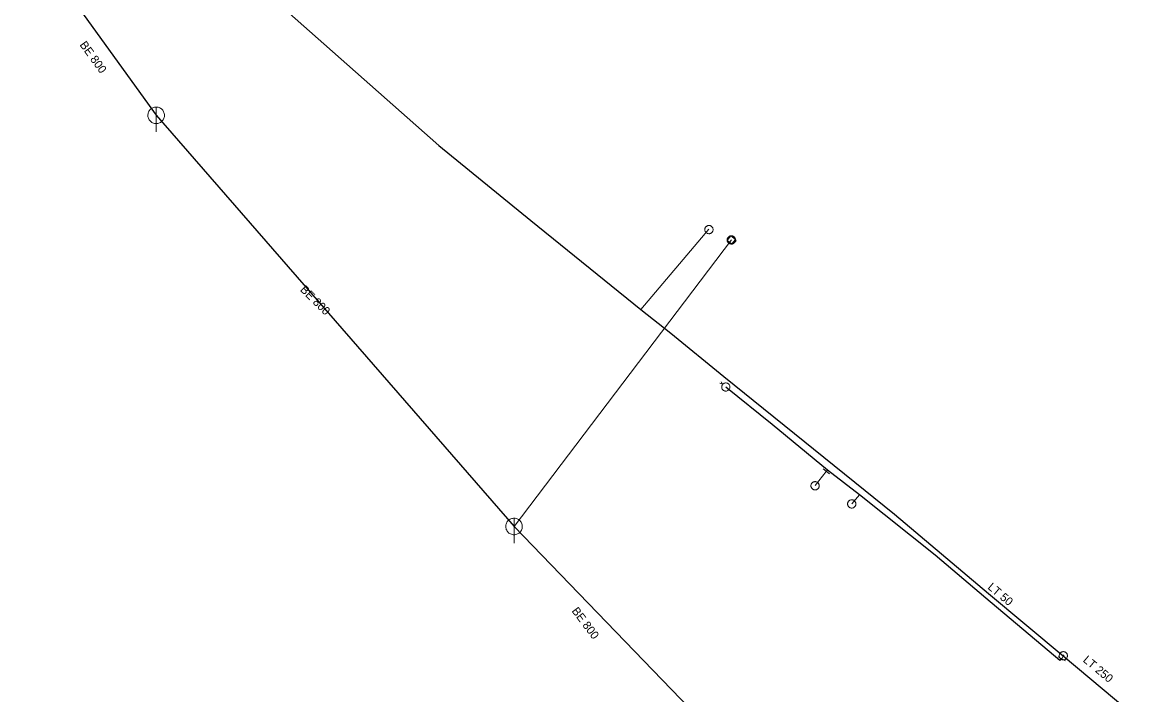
# Model space of a CAD drawing. Extents: x -807203 to -805207, y -993656 to -992505.
# Drawn here: x -805956 to -805822.4, y -993433.3 to -993352 of the extents above; entities that cross this region are included whole.
import ezdxf

# ---------------------------------------------------------------- set-up
doc = ezdxf.new("R2010")
doc.units = 0
doc.header["$LTSCALE"] = 0.4
doc.header["$PDMODE"] = 32
doc.header["$PDSIZE"] = 0.2
for name, color, linetype, lineweight in [('1', 7, 'Continuous', 13), ('11', 7, 'Continuous', 13), ('13', 7, 'Continuous', 13), ('14', 7, 'Continuous', 25), ('17', 7, 'Continuous', 25), ('22', 7, 'Continuous', 13), ('23', 7, 'Continuous', 13), ('34', 7, 'Continuous', 13), ('47', 7, 'Continuous', 13)]:
    doc.layers.add(name, color=color, linetype=linetype, lineweight=lineweight)

msp = doc.modelspace()

# ---------------------------------------------------------------- linework, layer by layer
at = {"layer": '11'}
msp.add_line((-805870.333, -993378.295), (-805896.59, -993412.94), dxfattribs=at)
at = {"layer": '13'}
for p, q in [((-805881.298, -993386.71), (-805873.059, -993377.03)), ((-805858.888, -993406.276), (-805860.249, -993407.99)), ((-805854.899, -993409.109), (-805855.822, -993410.186))]:
    msp.add_line(p, q, dxfattribs=at)
at = {"layer": '14'}
for p, q in [((-805951.2, -993347.419), (-805939.8, -993363.25)), ((-805939.8, -993363.25), (-805896.59, -993412.94)), ((-805896.59, -993412.94), (-805874.241, -993436.109))]:
    msp.add_line(p, q, dxfattribs=at)
at = {"layer": '14', "lineweight": 13}
for p, q in [((-805858.888, -993406.276), (-805858.765, -993406.12)), ((-805830.275, -993428.564), (-805830.473, -993428.943))]:
    msp.add_line(p, q, dxfattribs=at)
at = {"layer": '17'}
msp.add_line((-805830.275, -993428.564), (-805822.361, -993435.213), dxfattribs=at)
for points in [[(-805980.27, -993297.811), (-805964.539, -993313.096), (-805944.059, -993332.754), (-805925.796, -993349.072), (-805905.688, -993366.883), (-805894.556, -993375.978), (-805881.298, -993386.71), (-805877.651, -993389.561), (-805871.269, -993394.798), (-805850.666, -993411.467), (-805839.3, -993421.037), (-805830.275, -993428.564)], [(-805830.473, -993428.943), (-805830.693, -993429.142), (-805839.629, -993421.616), (-805845.743, -993416.397), (-805854.899, -993409.109), (-805858.765, -993406.12), (-805865.421, -993400.636), (-805871.024, -993396.088)]]:
    msp.add_lwpolyline(points, dxfattribs=at)
at = {"layer": '22'}
for p, q in [((-805939.8, -993365.25), (-805939.799, -993362.25)), ((-805896.59, -993414.94), (-805896.589, -993411.94))]:
    msp.add_line(p, q, dxfattribs=at)
for points in [[(-805938.8, -993363.25), (-805938.805, -993363.141), (-805938.823, -993363.033), (-805938.853, -993362.927), (-805938.893, -993362.826), (-805938.945, -993362.729), (-805939.007, -993362.639), (-805939.079, -993362.556), (-805939.159, -993362.482), (-805939.247, -993362.416), (-805939.341, -993362.361), (-805939.441, -993362.316), (-805939.546, -993362.283), (-805939.653, -993362.261), (-805939.762, -993362.251), (-805939.872, -993362.253), (-805939.98, -993362.267), (-805940.087, -993362.292), (-805940.19, -993362.329), (-805940.288, -993362.378), (-805940.38, -993362.436), (-805940.466, -993362.505), (-805940.543, -993362.582), (-805940.612, -993362.668), (-805940.671, -993362.76), (-805940.719, -993362.858), (-805940.756, -993362.961), (-805940.782, -993363.068), (-805940.796, -993363.176), (-805940.799, -993363.286), (-805940.789, -993363.395), (-805940.768, -993363.502), (-805940.734, -993363.606), (-805940.69, -993363.706), (-805940.635, -993363.801), (-805940.569, -993363.889), (-805940.495, -993363.969), (-805940.412, -993364.041), (-805940.322, -993364.103), (-805940.226, -993364.155), (-805940.124, -993364.196), (-805940.019, -993364.226), (-805939.911, -993364.244), (-805939.801, -993364.25), (-805939.692, -993364.244), (-805939.584, -993364.226), (-805939.479, -993364.197), (-805939.377, -993364.156), (-805939.28, -993364.104), (-805939.19, -993364.042), (-805939.107, -993363.971), (-805939.032, -993363.891), (-805938.967, -993363.803), (-805938.911, -993363.709), (-805938.867, -993363.609), (-805938.833, -993363.505), (-805938.811, -993363.397), (-805938.801, -993363.288)], [(-805870.047, -993377.922), (-805870.089, -993377.891), (-805870.137, -993377.866), (-805870.184, -993377.845), (-805870.234, -993377.829), (-805870.285, -993377.819), (-805870.339, -993377.814), (-805870.39, -993377.815), (-805870.442, -993377.822), (-805870.493, -993377.831), (-805870.543, -993377.848), (-805870.591, -993377.87), (-805870.634, -993377.897), (-805870.677, -993377.927), (-805870.717, -993377.964), (-805870.749, -993378.003), (-805870.78, -993378.045), (-805870.806, -993378.092), (-805870.827, -993378.14), (-805870.843, -993378.189), (-805870.852, -993378.24), (-805870.857, -993378.293), (-805870.857, -993378.345), (-805870.851, -993378.397), (-805870.841, -993378.448), (-805870.824, -993378.497), (-805870.801, -993378.546), (-805870.775, -993378.59), (-805870.745, -993378.632), (-805870.707, -993378.67), (-805870.669, -993378.704), (-805870.626, -993378.734), (-805870.58, -993378.761), (-805870.533, -993378.783), (-805870.483, -993378.797), (-805870.432, -993378.807), (-805870.379, -993378.813), (-805870.327, -993378.812), (-805870.275, -993378.806), (-805870.224, -993378.795), (-805870.174, -993378.779), (-805870.126, -993378.756), (-805870.082, -993378.73), (-805870.039, -993378.699), (-805870.001, -993378.663), (-805869.967, -993378.625), (-805869.937, -993378.582), (-805869.911, -993378.535), (-805869.889, -993378.488), (-805869.875, -993378.438), (-805869.864, -993378.386), (-805869.859, -993378.334), (-805869.859, -993378.283), (-805869.866, -993378.231), (-805869.876, -993378.179), (-805869.893, -993378.129), (-805869.915, -993378.081), (-805869.941, -993378.037), (-805869.972, -993377.995), (-805870.009, -993377.955)], [(-805870.85, -993378.37), (-805870.41, -993377.815), (-805869.867, -993378.246), (-805870.308, -993378.801)], [(-805895.59, -993412.94), (-805895.595, -993412.831), (-805895.613, -993412.723), (-805895.643, -993412.617), (-805895.683, -993412.516), (-805895.735, -993412.419), (-805895.797, -993412.329), (-805895.869, -993412.246), (-805895.949, -993412.172), (-805896.037, -993412.106), (-805896.131, -993412.051), (-805896.231, -993412.006), (-805896.336, -993411.973), (-805896.443, -993411.951), (-805896.552, -993411.941), (-805896.662, -993411.943), (-805896.77, -993411.957), (-805896.877, -993411.982), (-805896.98, -993412.019), (-805897.078, -993412.068), (-805897.17, -993412.126), (-805897.256, -993412.195), (-805897.333, -993412.272), (-805897.402, -993412.358), (-805897.461, -993412.45), (-805897.509, -993412.548), (-805897.546, -993412.651), (-805897.572, -993412.758), (-805897.586, -993412.866), (-805897.589, -993412.976), (-805897.579, -993413.085), (-805897.558, -993413.192), (-805897.524, -993413.296), (-805897.48, -993413.396), (-805897.425, -993413.491), (-805897.359, -993413.579), (-805897.285, -993413.659), (-805897.202, -993413.731), (-805897.112, -993413.793), (-805897.016, -993413.845), (-805896.914, -993413.886), (-805896.809, -993413.916), (-805896.701, -993413.934), (-805896.591, -993413.94), (-805896.482, -993413.934), (-805896.374, -993413.916), (-805896.269, -993413.887), (-805896.167, -993413.846), (-805896.07, -993413.794), (-805895.98, -993413.732), (-805895.897, -993413.661), (-805895.822, -993413.581), (-805895.757, -993413.493), (-805895.701, -993413.399), (-805895.657, -993413.299), (-805895.623, -993413.195), (-805895.601, -993413.087), (-805895.591, -993412.978)]]:
    msp.add_lwpolyline(points, close=True, dxfattribs=at)
msp.add_point((-805869.868, -993378.416), dxfattribs=at)
at = {"layer": '23'}
for points in [[(-805872.736, -993376.678), (-805872.778, -993376.646), (-805872.824, -993376.619), (-805872.871, -993376.598), (-805872.92, -993376.581), (-805872.971, -993376.57), (-805873.024, -993376.564), (-805873.076, -993376.563), (-805873.127, -993376.568), (-805873.179, -993376.578), (-805873.229, -993376.593), (-805873.277, -993376.613), (-805873.324, -993376.64), (-805873.366, -993376.669), (-805873.404, -993376.704), (-805873.44, -993376.741), (-805873.472, -993376.785), (-805873.499, -993376.828), (-805873.521, -993376.878), (-805873.538, -993376.925), (-805873.55, -993376.976), (-805873.555, -993377.03), (-805873.555, -993377.082), (-805873.551, -993377.135), (-805873.541, -993377.186), (-805873.525, -993377.235), (-805873.504, -993377.283), (-805873.479, -993377.328), (-805873.448, -993377.371), (-805873.413, -993377.41), (-805873.376, -993377.446), (-805873.334, -993377.478), (-805873.289, -993377.505), (-805873.241, -993377.527), (-805873.192, -993377.544), (-805873.142, -993377.554), (-805873.089, -993377.56), (-805873.037, -993377.562), (-805872.984, -993377.557), (-805872.933, -993377.546)], [(-805873.521, -993376.878), (-805873.538, -993376.925), (-805873.55, -993376.976), (-805873.555, -993377.03), (-805873.555, -993377.082), (-805873.551, -993377.135), (-805873.541, -993377.186), (-805873.525, -993377.235), (-805873.504, -993377.283), (-805873.479, -993377.328), (-805873.448, -993377.371), (-805873.413, -993377.41), (-805873.376, -993377.446), (-805873.334, -993377.478), (-805873.289, -993377.505), (-805873.241, -993377.527), (-805873.192, -993377.544), (-805873.142, -993377.554), (-805873.089, -993377.56), (-805873.037, -993377.562), (-805872.984, -993377.557), (-805872.933, -993377.546), (-805872.884, -993377.532), (-805872.835, -993377.51), (-805872.789, -993377.486), (-805872.747, -993377.454), (-805872.708, -993377.42), (-805872.672, -993377.382), (-805872.642, -993377.34), (-805872.614, -993377.295), (-805872.592, -993377.247), (-805872.576, -993377.197), (-805872.564, -993377.146), (-805872.557, -993377.095), (-805872.558, -993377.042), (-805872.561, -993376.991), (-805872.572, -993376.94), (-805872.587, -993376.888), (-805872.608, -993376.84), (-805872.634, -993376.795)], [(-805872.933, -993377.546), (-805872.884, -993377.532), (-805872.835, -993377.51), (-805872.789, -993377.486), (-805872.747, -993377.454), (-805872.708, -993377.42), (-805872.672, -993377.382), (-805872.642, -993377.34), (-805872.614, -993377.295), (-805872.592, -993377.247), (-805872.576, -993377.197), (-805872.564, -993377.146), (-805872.557, -993377.095), (-805872.558, -993377.042), (-805872.561, -993376.991), (-805872.572, -993376.94), (-805872.587, -993376.888), (-805872.608, -993376.84), (-805872.634, -993376.795), (-805872.665, -993376.753), (-805872.698, -993376.714), (-805872.736, -993376.678), (-805872.778, -993376.646), (-805872.824, -993376.619), (-805872.871, -993376.598), (-805872.92, -993376.581), (-805872.971, -993376.57), (-805873.024, -993376.564), (-805873.076, -993376.563), (-805873.127, -993376.568), (-805873.179, -993376.578), (-805873.229, -993376.593), (-805873.277, -993376.613), (-805873.324, -993376.64), (-805873.366, -993376.669), (-805873.404, -993376.704), (-805873.44, -993376.741), (-805873.472, -993376.785), (-805873.499, -993376.828), (-805873.521, -993376.878)], [(-805872.634, -993376.795), (-805872.665, -993376.753), (-805872.698, -993376.714), (-805872.736, -993376.678)], [(-805871.597, -993395.455), (-805871.428, -993395.735), (-805871.731, -993395.611)], [(-805859.925, -993407.639), (-805859.967, -993407.607), (-805860.012, -993407.58), (-805860.059, -993407.559), (-805860.109, -993407.542), (-805860.159, -993407.53), (-805860.212, -993407.524), (-805860.264, -993407.523), (-805860.316, -993407.528), (-805860.367, -993407.537), (-805860.417, -993407.552), (-805860.466, -993407.573), (-805860.512, -993407.599), (-805860.555, -993407.628), (-805860.593, -993407.662), (-805860.629, -993407.7), (-805860.661, -993407.744), (-805860.688, -993407.787), (-805860.71, -993407.836), (-805860.727, -993407.883), (-805860.74, -993407.935), (-805860.745, -993407.988), (-805860.746, -993408.04), (-805860.741, -993408.093), (-805860.732, -993408.144), (-805860.716, -993408.193), (-805860.695, -993408.242), (-805860.67, -993408.287), (-805860.64, -993408.33), (-805860.605, -993408.369), (-805860.567, -993408.405), (-805860.526, -993408.437), (-805860.48, -993408.464), (-805860.433, -993408.486), (-805860.384, -993408.503), (-805860.333, -993408.513), (-805860.281, -993408.52), (-805860.228, -993408.522), (-805860.176, -993408.517), (-805860.125, -993408.507)], [(-805860.71, -993407.836), (-805860.727, -993407.883), (-805860.74, -993407.935), (-805860.745, -993407.988), (-805860.746, -993408.04), (-805860.741, -993408.093), (-805860.732, -993408.144), (-805860.716, -993408.193), (-805860.695, -993408.242), (-805860.67, -993408.287), (-805860.64, -993408.33), (-805860.605, -993408.369), (-805860.567, -993408.405), (-805860.526, -993408.437), (-805860.48, -993408.464), (-805860.433, -993408.486), (-805860.384, -993408.503), (-805860.333, -993408.513), (-805860.281, -993408.52), (-805860.228, -993408.522), (-805860.176, -993408.517), (-805860.125, -993408.507), (-805860.075, -993408.492), (-805860.027, -993408.471), (-805859.981, -993408.447), (-805859.938, -993408.415), (-805859.9, -993408.381), (-805859.864, -993408.343), (-805859.833, -993408.301), (-805859.805, -993408.256), (-805859.782, -993408.209), (-805859.766, -993408.159), (-805859.754, -993408.108), (-805859.747, -993408.057), (-805859.748, -993408.004), (-805859.751, -993407.952), (-805859.761, -993407.901), (-805859.777, -993407.85), (-805859.797, -993407.802), (-805859.823, -993407.756)], [(-805860.125, -993408.507), (-805860.075, -993408.492), (-805860.027, -993408.471), (-805859.981, -993408.447), (-805859.938, -993408.415), (-805859.9, -993408.381), (-805859.864, -993408.343), (-805859.833, -993408.301), (-805859.805, -993408.256), (-805859.782, -993408.209), (-805859.766, -993408.159), (-805859.754, -993408.108), (-805859.747, -993408.057), (-805859.748, -993408.004), (-805859.751, -993407.952), (-805859.761, -993407.901), (-805859.777, -993407.85), (-805859.797, -993407.802), (-805859.823, -993407.756), (-805859.854, -993407.714), (-805859.887, -993407.675), (-805859.925, -993407.639), (-805859.967, -993407.607), (-805860.012, -993407.58), (-805860.059, -993407.559), (-805860.109, -993407.542), (-805860.159, -993407.53), (-805860.212, -993407.524), (-805860.264, -993407.523), (-805860.316, -993407.528), (-805860.367, -993407.537), (-805860.417, -993407.552), (-805860.466, -993407.573), (-805860.512, -993407.599), (-805860.555, -993407.628), (-805860.593, -993407.662), (-805860.629, -993407.7), (-805860.661, -993407.744), (-805860.688, -993407.787), (-805860.71, -993407.836)], [(-805859.823, -993407.756), (-805859.854, -993407.714), (-805859.887, -993407.675), (-805859.925, -993407.639)], [(-805855.498, -993409.835), (-805855.54, -993409.803), (-805855.585, -993409.776), (-805855.632, -993409.755), (-805855.682, -993409.738), (-805855.732, -993409.726), (-805855.785, -993409.72), (-805855.837, -993409.719), (-805855.889, -993409.724), (-805855.94, -993409.733), (-805855.99, -993409.748), (-805856.039, -993409.769), (-805856.085, -993409.795), (-805856.128, -993409.824), (-805856.166, -993409.858), (-805856.202, -993409.896), (-805856.234, -993409.94), (-805856.261, -993409.983), (-805856.283, -993410.032), (-805856.3, -993410.079), (-805856.313, -993410.131), (-805856.318, -993410.184), (-805856.319, -993410.236), (-805856.314, -993410.289), (-805856.305, -993410.34), (-805856.289, -993410.389), (-805856.268, -993410.438), (-805856.243, -993410.483), (-805856.213, -993410.526), (-805856.178, -993410.565), (-805856.14, -993410.601), (-805856.099, -993410.633), (-805856.053, -993410.66), (-805856.006, -993410.682), (-805855.957, -993410.699), (-805855.906, -993410.709), (-805855.854, -993410.716), (-805855.801, -993410.718), (-805855.749, -993410.713), (-805855.698, -993410.703)], [(-805856.283, -993410.032), (-805856.3, -993410.079), (-805856.313, -993410.131), (-805856.318, -993410.184), (-805856.319, -993410.236), (-805856.314, -993410.289), (-805856.305, -993410.34), (-805856.289, -993410.389), (-805856.268, -993410.438), (-805856.243, -993410.483), (-805856.213, -993410.526), (-805856.178, -993410.565), (-805856.14, -993410.601), (-805856.099, -993410.633), (-805856.053, -993410.66), (-805856.006, -993410.682), (-805855.957, -993410.699), (-805855.906, -993410.709), (-805855.854, -993410.716), (-805855.801, -993410.718), (-805855.749, -993410.713), (-805855.698, -993410.703), (-805855.648, -993410.688), (-805855.6, -993410.667), (-805855.554, -993410.643), (-805855.511, -993410.611), (-805855.473, -993410.577), (-805855.437, -993410.539), (-805855.406, -993410.497), (-805855.378, -993410.452), (-805855.355, -993410.405), (-805855.339, -993410.355), (-805855.327, -993410.304), (-805855.32, -993410.253), (-805855.321, -993410.2), (-805855.324, -993410.148), (-805855.334, -993410.097), (-805855.35, -993410.046), (-805855.37, -993409.998), (-805855.396, -993409.952)], [(-805855.698, -993410.703), (-805855.648, -993410.688), (-805855.6, -993410.667), (-805855.554, -993410.643), (-805855.511, -993410.611), (-805855.473, -993410.577), (-805855.437, -993410.539), (-805855.406, -993410.497), (-805855.378, -993410.452), (-805855.355, -993410.405), (-805855.339, -993410.355), (-805855.327, -993410.304), (-805855.32, -993410.253), (-805855.321, -993410.2), (-805855.324, -993410.148), (-805855.334, -993410.097), (-805855.35, -993410.046), (-805855.37, -993409.998), (-805855.396, -993409.952), (-805855.427, -993409.91), (-805855.46, -993409.871), (-805855.498, -993409.835), (-805855.54, -993409.803), (-805855.585, -993409.776), (-805855.632, -993409.755), (-805855.682, -993409.738), (-805855.732, -993409.726), (-805855.785, -993409.72), (-805855.837, -993409.719), (-805855.889, -993409.724), (-805855.94, -993409.733), (-805855.99, -993409.748), (-805856.039, -993409.769), (-805856.085, -993409.795), (-805856.128, -993409.824), (-805856.166, -993409.858), (-805856.202, -993409.896), (-805856.234, -993409.94), (-805856.261, -993409.983), (-805856.283, -993410.032)], [(-805855.396, -993409.952), (-805855.427, -993409.91), (-805855.46, -993409.871), (-805855.498, -993409.835)]]:
    msp.add_lwpolyline(points, dxfattribs=at)
msp.add_lwpolyline([(-805870.699, -993395.71), (-805870.761, -993395.664), (-805870.83, -993395.629), (-805870.904, -993395.604), (-805870.98, -993395.592), (-805871.057, -993395.591), (-805871.134, -993395.602), (-805871.207, -993395.625), (-805871.276, -993395.659), (-805871.339, -993395.704), (-805871.395, -993395.757), (-805871.442, -993395.819), (-805871.479, -993395.887), (-805871.505, -993395.96), (-805871.518, -993396.035), (-805871.52, -993396.113), (-805871.51, -993396.189), (-805871.489, -993396.264), (-805871.456, -993396.333), (-805871.413, -993396.397), (-805871.361, -993396.454), (-805871.3, -993396.501), (-805871.232, -993396.539), (-805871.159, -993396.566), (-805871.084, -993396.582), (-805871.007, -993396.585), (-805870.93, -993396.577), (-805870.856, -993396.557), (-805870.785, -993396.525), (-805870.72, -993396.483), (-805870.663, -993396.432), (-805870.614, -993396.371), (-805870.575, -993396.304), (-805870.547, -993396.233), (-805870.53, -993396.158), (-805870.526, -993396.081), (-805870.532, -993396.004), (-805870.551, -993395.929), (-805870.581, -993395.858), (-805870.622, -993395.792), (-805870.672, -993395.734)], close=True, dxfattribs=at)
at = {"layer": '34'}
for p, q in [((-805859.279, -993405.965), (-805858.496, -993406.587)), ((-805830.916, -993428.711), (-805830.03, -993429.174))]:
    msp.add_line(p, q, dxfattribs=at)
at = {"layer": '47'}
for points in [[(-805829.891, -993428.884), (-805829.86, -993428.842), (-805829.832, -993428.797), (-805829.811, -993428.749), (-805829.794, -993428.7), (-805829.782, -993428.649), (-805829.776, -993428.596), (-805829.776, -993428.545), (-805829.78, -993428.493), (-805829.79, -993428.442), (-805829.805, -993428.391), (-805829.826, -993428.343), (-805829.852, -993428.297), (-805829.881, -993428.255), (-805829.916, -993428.215), (-805829.954, -993428.18), (-805829.996, -993428.149), (-805830.041, -993428.121), (-805830.089, -993428.099), (-805830.138, -993428.083), (-805830.189, -993428.071), (-805830.242, -993428.065), (-805830.294, -993428.064), (-805830.346, -993428.069), (-805830.397, -993428.078), (-805830.447, -993428.094), (-805830.495, -993428.115), (-805830.541, -993428.14), (-805830.583, -993428.17), (-805830.623, -993428.205), (-805830.658, -993428.243), (-805830.689, -993428.285), (-805830.717, -993428.33), (-805830.739, -993428.378), (-805830.755, -993428.427), (-805830.767, -993428.478), (-805830.774, -993428.53), (-805830.775, -993428.583), (-805830.77, -993428.635), (-805830.76, -993428.686), (-805830.744, -993428.736), (-805830.723, -993428.784), (-805830.698, -993428.83), (-805830.668, -993428.872), (-805830.633, -993428.912), (-805830.595, -993428.947), (-805830.553, -993428.978), (-805830.508, -993429.006), (-805830.461, -993429.028), (-805830.411, -993429.044), (-805830.36, -993429.056), (-805830.308, -993429.063), (-805830.256, -993429.063), (-805830.204, -993429.058), (-805830.153, -993429.048), (-805830.102, -993429.033), (-805830.054, -993429.012), (-805830.009, -993428.987), (-805829.966, -993428.957), (-805829.926, -993428.922)], [(-805830.212, -993428.616), (-805830.206, -993428.609), (-805830.202, -993428.602), (-805830.199, -993428.594), (-805830.196, -993428.586), (-805830.194, -993428.577), (-805830.193, -993428.569), (-805830.192, -993428.56), (-805830.193, -993428.552), (-805830.195, -993428.544), (-805830.198, -993428.535), (-805830.201, -993428.527), (-805830.205, -993428.52), (-805830.21, -993428.513), (-805830.215, -993428.506), (-805830.222, -993428.501), (-805830.229, -993428.495), (-805830.236, -993428.491), (-805830.244, -993428.488), (-805830.252, -993428.485), (-805830.261, -993428.483), (-805830.269, -993428.482), (-805830.278, -993428.481), (-805830.286, -993428.482), (-805830.295, -993428.484), (-805830.303, -993428.487), (-805830.311, -993428.49), (-805830.318, -993428.494), (-805830.325, -993428.499), (-805830.332, -993428.504), (-805830.337, -993428.511), (-805830.343, -993428.518), (-805830.347, -993428.525), (-805830.35, -993428.533), (-805830.353, -993428.541), (-805830.355, -993428.55), (-805830.357, -993428.557), (-805830.357, -993428.567), (-805830.356, -993428.575), (-805830.354, -993428.584), (-805830.351, -993428.592), (-805830.348, -993428.6), (-805830.344, -993428.607), (-805830.339, -993428.614), (-805830.334, -993428.621), (-805830.327, -993428.626), (-805830.32, -993428.632), (-805830.313, -993428.636), (-805830.305, -993428.639), (-805830.297, -993428.642), (-805830.288, -993428.644), (-805830.281, -993428.646), (-805830.271, -993428.646), (-805830.263, -993428.645), (-805830.255, -993428.643), (-805830.246, -993428.64), (-805830.238, -993428.637), (-805830.231, -993428.633), (-805830.224, -993428.628), (-805830.217, -993428.623)]]:
    msp.add_lwpolyline(points, close=True, dxfattribs=at)

# ---------------------------------------------------------------- texts
at = {"layer": '1'}
for s, rotation, p in [('BE 800', 306, (-805949.09, -993354.738)), ('BE 800', 315, (-805922.49, -993384.392)), ('LT 50 ', 320, (-805839.489, -993420.401)), ('BE 800', 307, (-805889.683, -993423.158)), ('LT 250', 320, (-805827.98, -993429.205))]:
    msp.add_text(s, height=1, rotation=rotation, dxfattribs=at).set_placement(p)

doc.saveas('drawing.dxf')
